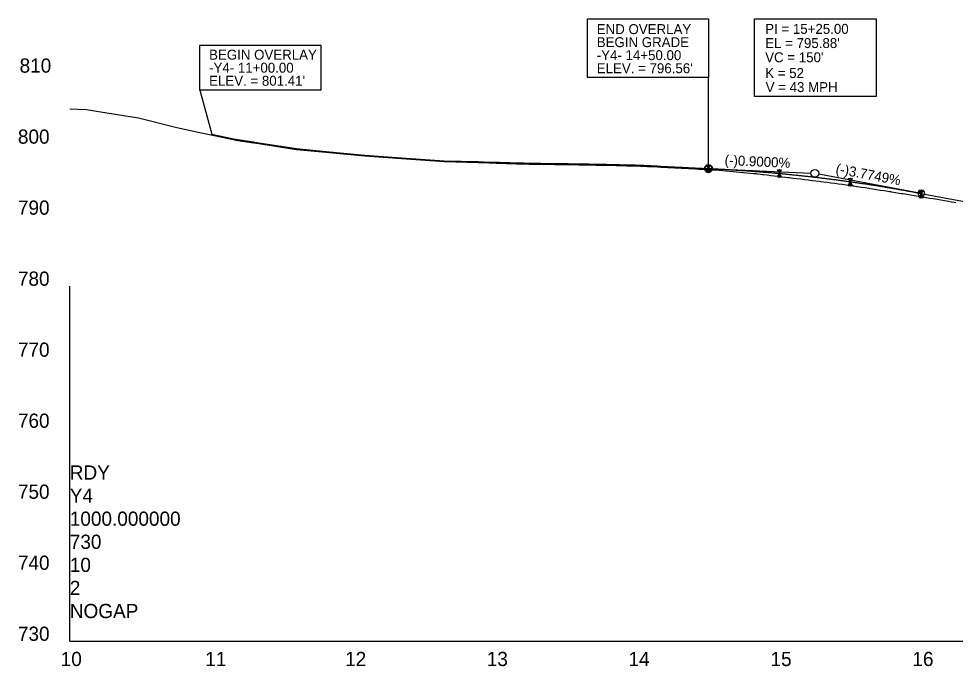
# Model space of a CAD drawing. Extents: x 579185 to 595036, y -53221 to -44640.
# Drawn here: x 582946 to 583606, y -49553 to -49097 of the extents above; entities that cross this region are included whole.
import ezdxf

# ---------------------------------------------------------------- set-up
doc = ezdxf.new("R2010")
doc.units = 0
for name, color, linetype in [('Exist Profile Cell', 7, 'Continuous'), ('Exist Vertical Profile Ground Line', 7, 'Continuous'), ('Exist Vertical Profile Horizontal Axis Label Major', 7, 'Continuous'), ('Exist Vertical Profile Vertical Axis Label', 7, 'Continuous'), ('Old_Level_2', 7, 'Continuous'), ('Prop Grid Mask', 7, 'Continuous'), ('Prop Vertical Profile Curve Label', 7, 'Continuous'), ('Prop Vertical Profile Grade', 7, 'Continuous'), ('Prop Vertical Profile Grade Label', 7, 'Continuous'), ('Prop VPI Label', 7, 'Continuous')]:
    doc.layers.add(name, color=color, linetype=linetype)

msp = doc.modelspace()

# ---------------------------------------------------------------- linework, layer by layer
at = {"layer": 'Exist Profile Cell'}
for q in [(582981.74, -49285.12), (584272.59, -49535.12), (582981.74, -49535.12)]:
    msp.add_line((582981.74, -49535.12), q, dxfattribs=at)
at = {"layer": 'Exist Vertical Profile Ground Line'}
for points in [[(582981.74, -49160.31), (582993.6, -49160.83), (583000.63, -49161.93), (583030.25, -49166.59), (583057.2, -49173.35), (583068.07, -49175.71), (583069.01, -49175.93), (583098.09, -49182.22), (583098.56, -49182.31), (583111.15, -49184.24), (583111.82, -49184.37), (583141.47, -49188.87), (583159.63, -49190.63), (583189.59, -49193.52), (583215.54, -49195.34), (583245.57, -49197.44), (583269.43, -49198.14), (583277.36, -49198.37), (583279.78, -49198.44), (583282.2, -49198.51), (583284.61, -49198.59), (583287.03, -49198.66), (583289.45, -49198.74), (583291.87, -49198.81), (583293.14, -49198.85), (583294.29, -49198.88), (583296.7, -49198.94), (583299.12, -49199), (583301.54, -49199.06), (583303.96, -49199.12), (583305.49, -49199.16), (583306.38, -49199.17), (583308.79, -49199.2), (583311.21, -49199.24), (583313.63, -49199.28), (583316.05, -49199.31), (583318.54, -49199.35), (583318.94, -49199.36), (583320.89, -49199.38), (583323.3, -49199.41), (583325.72, -49199.45), (583328.14, -49199.48), (583330.56, -49199.51), (583332.98, -49199.55), (583335.39, -49199.58), (583337.81, -49199.62), (583340.23, -49199.66), (583342.65, -49199.69), (583344.32, -49199.72), (583345.07, -49199.73), (583347.48, -49199.77), (583349.9, -49199.82), (583352.32, -49199.86), (583354.74, -49199.9), (583357.16, -49199.95), (583359.58, -49200), (583362.4, -49200.05), (583364.41, -49200.09), (583366.83, -49200.15), (583369.25, -49200.21), (583371.67, -49200.27), (583374.08, -49200.33), (583376.5, -49200.39), (583378.92, -49200.45), (583379.94, -49200.47), (583380.35, -49200.48), (583381.34, -49200.52), (583383.76, -49200.62), (583386.17, -49200.72), (583388.59, -49200.82), (583391.01, -49200.92), (583392.39, -49200.97), (583393.43, -49201.03), (583395.85, -49201.17), (583398.27, -49201.3), (583400.68, -49201.43), (583403.1, -49201.56), (583405.52, -49201.69), (583407.94, -49201.82), (583410.36, -49201.95), (583412.77, -49202.08), (583413.32, -49202.11), (583414.34, -49202.13), (583415.19, -49202.18), (583417.61, -49202.3), (583420.03, -49202.43), (583422.45, -49202.56), (583424.86, -49202.68), (583427.28, -49202.81), (583429.7, -49202.93), (583432.12, -49203.05), (583434.67, -49203.18), (583435.81, -49203.28), (583436.96, -49203.37), (583439.37, -49203.59), (583441.79, -49203.81), (583444.21, -49204.03), (583446.63, -49204.25), (583449.05, -49204.47), (583451.46, -49204.69), (583453.88, -49204.91)], [(583453.88, -49204.91), (583456.3, -49205.13), (583458.72, -49205.35), (583461.14, -49205.56), (583463.56, -49205.78), (583465.44, -49205.95), (583465.97, -49206.01), (583468.39, -49206.29), (583469.76, -49206.45), (583470.81, -49206.58), (583473.23, -49206.87), (583475.65, -49207.17), (583478.06, -49207.47), (583480.73, -49207.79), (583483.4, -49208.12), (583486.07, -49208.45), (583487.74, -49208.65), (583488.74, -49208.77), (583489.94, -49208.89), (583491.41, -49209.07), (583494.08, -49209.39), (583496.75, -49209.71), (583499.41, -49210.03), (583502.08, -49210.35), (583504.75, -49210.67), (583507.42, -49210.99), (583510.09, -49211.31), (583510.86, -49211.4), (583512.82, -49211.6), (583515.43, -49211.96), (583518.1, -49212.33), (583520.77, -49212.7), (583523.43, -49213.07), (583526.1, -49213.44), (583528.77, -49213.81), (583531.44, -49214.18), (583533.56, -49214.48), (583534.11, -49214.56), (583536.41, -49214.89), (583536.78, -49214.95), (583539.45, -49215.37), (583542.12, -49215.79), (583544.79, -49216.22), (583547.45, -49216.64), (583550.12, -49217.06), (583552.79, -49217.48), (583555.46, -49217.9), (583558.13, -49218.32), (583559.02, -49218.46), (583560.04, -49218.62), (583560.8, -49218.75), (583563.47, -49219.17), (583566.14, -49219.59), (583567.68, -49219.84), (583568.81, -49220.02), (583571.47, -49220.47), (583574.14, -49220.91), (583576.81, -49221.36), (583579.48, -49221.8), (583582.15, -49222.25), (583584.26, -49222.56), (583584.82, -49222.66), (583587.49, -49223.11), (583590.16, -49223.56), (583592.82, -49224.01), (583595.49, -49224.46), (583598.16, -49224.91), (583600.83, -49225.36), (583603.1, -49225.74), (583603.5, -49225.8), (583606.17, -49226.2)]]:
    msp.add_lwpolyline(points, dxfattribs=at)
at = {"layer": 'Old_Level_2'}
for p, q in [((583431.74, -49202.33), (583430.3, -49199.83)), ((583430.3, -49199.83), (583433.19, -49199.83)), ((583430.3, -49204.83), (583431.74, -49202.33)), ((583430.78, -49200.66), (583432.71, -49200.66)), ((583431.26, -49201.49), (583432.23, -49201.49)), ((583431.74, -49202.33), (583433.19, -49199.83)), ((583433.19, -49204.83), (583431.74, -49202.33)), ((583430.3, -49204.83), (583433.19, -49204.83)), ((583430.78, -49203.99), (583432.71, -49203.99)), ((583431.26, -49203.16), (583432.23, -49203.16)), ((583481.74, -49205.78), (583480.3, -49203.28)), ((583480.3, -49203.28), (583483.19, -49203.28)), ((583480.3, -49208.28), (583481.75, -49205.78)), ((583480.3, -49208.28), (583483.19, -49208.28)), ((583480.78, -49204.12), (583482.71, -49204.12)), ((583480.78, -49207.45), (583482.71, -49207.45)), ((583481.26, -49204.95), (583482.23, -49204.95)), ((583481.26, -49206.62), (583482.23, -49206.62)), ((583483.19, -49208.28), (583481.74, -49205.78)), ((583481.75, -49205.78), (583483.19, -49203.28)), ((583531.74, -49211.76), (583530.3, -49209.26)), ((583530.3, -49209.26), (583533.19, -49209.26)), ((583531.75, -49211.76), (583533.19, -49209.26)), ((583530.3, -49214.26), (583531.75, -49211.76)), ((583530.3, -49214.26), (583533.19, -49214.26)), ((583530.78, -49210.1), (583532.71, -49210.1)), ((583530.78, -49213.43), (583532.71, -49213.43)), ((583531.26, -49210.93), (583532.23, -49210.93)), ((583531.26, -49212.6), (583532.23, -49212.6)), ((583533.19, -49214.26), (583531.74, -49211.76)), ((583581.74, -49220.13), (583580.3, -49217.63)), ((583580.3, -49217.63), (583583.19, -49217.63)), ((583580.3, -49222.63), (583581.74, -49220.13)), ((583580.78, -49218.46), (583582.71, -49218.46)), ((583580.78, -49221.8), (583582.71, -49221.8)), ((583581.26, -49219.3), (583582.23, -49219.3)), ((583581.26, -49220.97), (583582.23, -49220.97)), ((583581.74, -49220.13), (583583.19, -49217.63)), ((583583.19, -49222.63), (583581.74, -49220.13)), ((583580.3, -49222.63), (583583.19, -49222.63))]:
    msp.add_line(p, q, dxfattribs=at)
at = {"layer": 'Prop Grid Mask'}
for points in [[(583346.48, -49096.99), (583431.88, -49096.99), (583431.88, -49138.31), (583346.48, -49138.31)], [(583464.26, -49096.89), (583550.04, -49096.89), (583550.04, -49151.7), (583464.26, -49151.7)], [(583073.34, -49115.39), (583158.71, -49115.39), (583158.71, -49147.13), (583073.34, -49147.13)]]:
    msp.add_lwpolyline(points, close=True, dxfattribs=at)
at = {"layer": 'Prop Vertical Profile Curve Label'}
for p, q in [((583431.74, -49202.41), (583431.88, -49138.31)), ((583073.34, -49147.13), (583081.74, -49178.04))]:
    msp.add_line(p, q, dxfattribs=at)
for centre in [(583431.74, -49202.33), (583431.74, -49202.33), (583581.74, -49219.86)]:
    msp.add_circle(centre, 2.25, dxfattribs=at)
at = {"layer": 'Prop Vertical Profile Grade'}
msp.add_line((583581.74, -49219.86), (583746.74, -49251), dxfattribs=at)
msp.add_lwpolyline([(583081.74, -49178.04), (583098.22, -49181.61), (583098.67, -49181.7), (583111.26, -49183.62), (583111.93, -49183.75), (583141.55, -49188.25), (583159.69, -49190.01), (583189.64, -49192.9), (583215.58, -49194.72), (583245.6, -49196.81), (583269.44, -49197.51), (583277.38, -49197.75), (583279.8, -49197.82), (583282.21, -49197.89), (583284.63, -49197.96), (583287.05, -49198.04), (583289.47, -49198.11), (583291.89, -49198.19), (583293.16, -49198.23), (583294.3, -49198.26), (583296.72, -49198.31), (583299.14, -49198.37), (583301.56, -49198.43), (583303.97, -49198.49), (583305.5, -49198.53), (583306.39, -49198.54), (583308.8, -49198.58), (583311.22, -49198.61), (583313.64, -49198.65), (583316.06, -49198.69), (583318.55, -49198.73), (583318.95, -49198.73), (583320.89, -49198.76), (583323.31, -49198.79), (583325.73, -49198.82), (583328.15, -49198.85), (583330.57, -49198.89), (583332.98, -49198.92), (583335.4, -49198.96), (583337.82, -49198.99), (583340.24, -49199.03), (583342.66, -49199.07), (583344.33, -49199.09), (583345.08, -49199.1), (583347.5, -49199.15), (583349.91, -49199.19), (583352.33, -49199.24), (583354.75, -49199.28), (583357.17, -49199.32), (583359.59, -49199.37), (583362.41, -49199.42), (583364.43, -49199.47), (583366.84, -49199.53), (583369.26, -49199.59), (583371.68, -49199.64), (583374.1, -49199.7), (583376.52, -49199.76), (583378.94, -49199.82), (583379.96, -49199.85), (583380.37, -49199.86), (583381.36, -49199.9), (583383.78, -49200), (583386.2, -49200.09), (583388.62, -49200.19), (583391.04, -49200.29), (583392.42, -49200.35), (583393.46, -49200.41), (583395.88, -49200.54), (583398.3, -49200.67), (583400.72, -49200.81), (583403.14, -49200.94), (583405.55, -49201.07), (583407.97, -49201.2), (583410.39, -49201.33), (583412.81, -49201.45), (583413.34, -49201.48), (583414.37, -49201.51), (583415.22, -49201.55), (583417.64, -49201.68), (583420.06, -49201.81), (583422.48, -49201.93), (583424.9, -49202.06), (583427.32, -49202.18), (583429.73, -49202.31), (583431.74, -49202.41)], dxfattribs=at)
msp.add_spline([(583431.74, -49202.33), (583434.74, -49202.47), (583437.74, -49202.61), (583440.74, -49202.77), (583443.74, -49202.94), (583446.74, -49203.11), (583449.74, -49203.29), (583452.74, -49203.48), (583455.74, -49203.68), (583458.74, -49203.89), (583461.74, -49204.11), (583464.74, -49204.33), (583467.74, -49204.57), (583470.74, -49204.81), (583473.74, -49205.06), (583476.74, -49205.32), (583479.74, -49205.59), (583482.74, -49205.87), (583485.74, -49206.15), (583488.74, -49206.45), (583491.74, -49206.75), (583494.74, -49207.06), (583497.74, -49207.38), (583500.74, -49207.71), (583503.74, -49208.05), (583506.74, -49208.4), (583509.74, -49208.75), (583512.74, -49209.12), (583515.74, -49209.49), (583518.74, -49209.87), (583521.74, -49210.26), (583524.74, -49210.66), (583527.74, -49211.06), (583530.74, -49211.48), (583533.74, -49211.9), (583536.74, -49212.33), (583539.74, -49212.78), (583542.74, -49213.22), (583545.74, -49213.68), (583548.74, -49214.15), (583551.74, -49214.63), (583554.74, -49215.11), (583557.74, -49215.6), (583560.74, -49216.1), (583563.74, -49216.62), (583566.74, -49217.13), (583569.74, -49217.66), (583572.74, -49218.2), (583575.74, -49218.74), (583578.74, -49219.3), (583581.74, -49219.86)], degree=3, dxfattribs=at)
at = {"layer": 'Prop VPI Label'}
for p, q in [((583431.74, -49202.33), (583504, -49205.58)), ((583581.74, -49219.86), (583509.45, -49206.21))]:
    msp.add_line(p, q, dxfattribs=at)
for centre in [(583431.74, -49202.33), (583431.74, -49202.33), (583506.74, -49205.7)]:
    msp.add_circle(centre, 2.75, dxfattribs=at)

# ---------------------------------------------------------------- texts
at = {"layer": 'Exist Profile Cell'}
for s, p in [('RDY', (582981.74, -49421.37)), ('Y4', (582981.74, -49437.62)), ('1000.000000', (582981.74, -49453.87)), ('730', (582981.74, -49470.12)), ('10', (582981.74, -49486.37)), ('2', (582981.74, -49502.62)), ('NOGAP', (582981.74, -49518.87))]:
    msp.add_text(s, height=10, dxfattribs=at).set_placement(p)
at = {"layer": 'Exist Vertical Profile Horizontal Axis Label Major'}
for s, p in [('10', (582975.33, -49552.62)), ('11', (583077.17, -49552.62)), ('12', (583175.72, -49552.62)), ('13', (583275.55, -49552.62)), ('14', (583375.39, -49552.62)), ('15', (583475.49, -49552.62)), ('16', (583575.43, -49552.62))]:
    msp.add_text(s, height=10, dxfattribs=at).set_placement(p)
at = {"layer": 'Exist Vertical Profile Vertical Axis Label'}
for s, p in [('810', (582946.37, -49134.87)), ('800', (582945.18, -49184.87)), ('790', (582945.18, -49234.87)), ('780', (582945.18, -49284.87)), ('770', (582945.18, -49334.87)), ('760', (582945.18, -49384.87)), ('750', (582945.18, -49434.87)), ('740', (582945.18, -49484.87)), ('730', (582945.18, -49534.87))]:
    msp.add_text(s, height=10, dxfattribs=at).set_placement(p)
at = {"layer": 'Old_Level_2'}
for p in [(583431.51, -49199.67), (583481.51, -49203.12), (583431.32, -49205.83), (583481.32, -49209.29), (583531.51, -49209.1), (583531.32, -49215.27), (583581.51, -49217.47), (583581.32, -49223.64)]:
    msp.add_text('6"', height=0.8, dxfattribs=at).set_placement(p)
at = {"layer": 'Prop Vertical Profile Curve Label'}
for s, p in [("VC = 150'", (583471.74, -49127.52)), ('K = 52', (583471.74, -49138.57)), ('V = 43 MPH', (583472.04, -49148.53))]:
    msp.add_text(s, height=7, dxfattribs=at).set_placement(p)
at = {"layer": 'Prop Vertical Profile Grade Label'}
for s, rotation, p in [('(-)0.9000%', 357.42343, (583443.02, -49199.83)), ('(-)3.7749%', 349.31136, (583521.02, -49205.68))]:
    msp.add_text(s, height=7, rotation=rotation, dxfattribs=at).set_placement(p)
at = {"layer": 'Prop VPI Label'}
for s, p in [('END OVERLAY', (583353.04, -49107.7)), ('PI = 15+25.00', (583471.74, -49107.52)), ('BEGIN GRADE', (583353.04, -49116.88)), ("EL = 795.88'", (583471.74, -49117.52)), ('BEGIN OVERLAY', (583079.89, -49125.7)), ('-Y4- 14+50.00', (583353.04, -49126.05)), ('-Y4- 11+00.00', (583079.89, -49134.88)), ("ELEV. = 796.56'", (583353.04, -49135.23)), ("ELEV. = 801.41'", (583079.89, -49144.05))]:
    msp.add_text(s, height=7, dxfattribs=at).set_placement(p)

doc.saveas('drawing.dxf')
